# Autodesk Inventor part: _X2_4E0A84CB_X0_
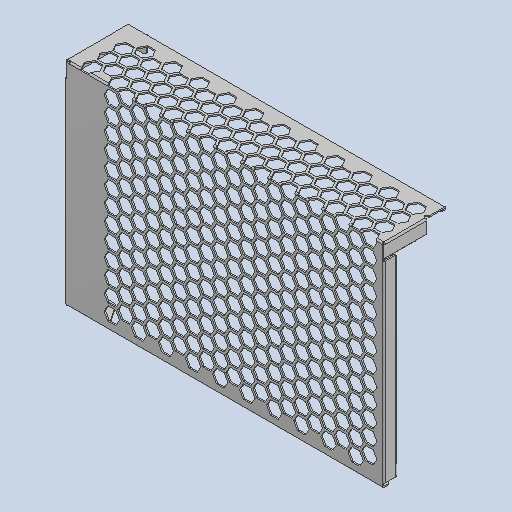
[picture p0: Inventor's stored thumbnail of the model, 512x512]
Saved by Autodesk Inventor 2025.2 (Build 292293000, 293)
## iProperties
Created: 2025-04
Part Number: _X2_4E0A84CB_X0_
Material: Generic
Description: NOT SPECIFIED
Document SubType Name: Modeling
Designer: BennF
Density: 1 g/cm^3
Appearance: Default
Author: BennF
Revision Number: 4LAST_VERSION
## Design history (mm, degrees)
feature "Base1"
body "Solid1"
